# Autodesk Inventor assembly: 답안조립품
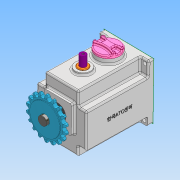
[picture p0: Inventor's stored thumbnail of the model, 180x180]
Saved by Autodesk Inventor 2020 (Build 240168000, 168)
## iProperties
Created: 2022-01
Part Number: 답안조립품
Document SubType Name: Assembly
Designer: user
Author: user
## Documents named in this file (16)
- C:\Users\user\Desktop\720112V1013\답안조립품.iam
- C:\Users\user\Desktop\720112V1013\멈춤나사 M3.ipt
- C:\Users\user\Desktop\720112V1013\메인 축.ipt
- C:\Users\user\Desktop\720112V1013\베어링 608.ipt
- C:\Users\user\Desktop\720112V1013\베어링 6003.ipt
- C:\Users\user\Desktop\720112V1013\본체.ipt
- C:\Users\user\Desktop\720112V1013\볼트 M4 x 10.ipt
- C:\Users\user\Desktop\720112V1013\부시.ipt
- C:\Users\user\Desktop\720112V1013\상부 캡.ipt
- C:\Users\user\Desktop\720112V1013\서브 축.ipt
- C:\Users\user\Desktop\720112V1013\스프로킷.ipt
- C:\Users\user\Desktop\720112V1013\슬라이더.ipt
- C:\Users\user\Desktop\720112V1013\오일 실 8 x 22 x 7.ipt
- C:\Users\user\Desktop\720112V1013\오일 실 17 x 32 x 8.ipt
- C:\Users\user\Desktop\720112V1013\커버.ipt
- C:\Users\user\Desktop\720112V1013\키 5 x 5.ipt
